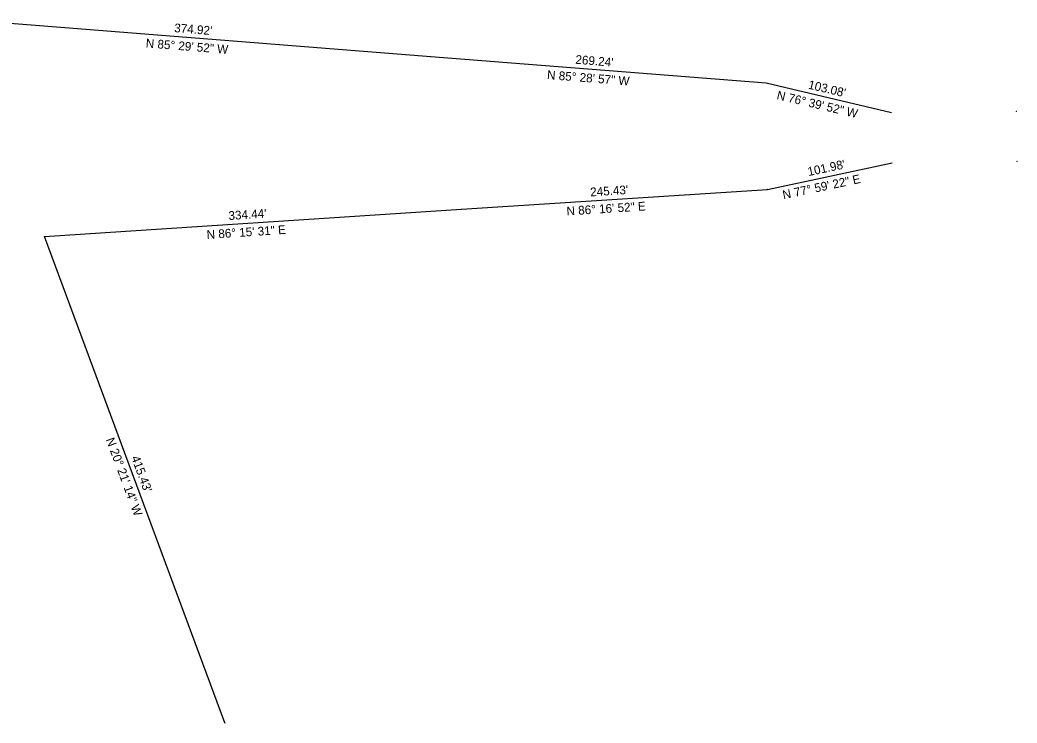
# Model space of a CAD drawing. Extents: x 179269 to 181170, y 300070 to 301262.
# Drawn here: x 180372 to 181170, y 300137 to 300700 of the extents above; entities that cross this region are included whole.
import ezdxf

# ---------------------------------------------------------------- set-up
doc = ezdxf.new("R2010")
doc.units = 0
for name, color, linetype in [('GK_Visualization', 7, 'Continuous'), ('RW_X_Fee_WL', 7, 'Continuous'), ('RW_X_Text', 7, 'Continuous')]:
    doc.layers.add(name, color=color, linetype=linetype)

msp = doc.modelspace()

# ---------------------------------------------------------------- linework, layer by layer
at = {"layer": 'GK_Visualization'}
for p, q in [((180700.4, 300670.33), (180326.63, 300699.76)), ((180700.4, 300670.33), (180326.63, 300699.76)), ((180700.33, 300670.27), (180700.46, 300670.4)), ((180700.33, 300670.4), (180700.46, 300670.27)), ((180968.79, 300649.13), (180700.4, 300670.33)), ((180968.79, 300649.13), (180700.4, 300670.33)), ((180968.73, 300649.06), (180968.86, 300649.19)), ((180968.73, 300649.19), (180968.86, 300649.06)), ((181069.09, 300625.35), (180968.79, 300649.13)), ((181069.09, 300625.35), (180968.79, 300649.13)), ((181169.02, 300626.51), (181169.15, 300626.64)), ((181169.02, 300626.64), (181169.15, 300626.51)), ((181069.03, 300625.28), (181069.16, 300625.42)), ((181069.03, 300625.42), (181069.16, 300625.28)), ((181169.51, 300586.51), (181169.64, 300586.64)), ((181169.51, 300586.64), (181169.64, 300586.51)), ((180969.83, 300564.13), (181069.58, 300585.35)), ((180969.83, 300564.13), (181069.58, 300585.35)), ((181069.52, 300585.29), (181069.65, 300585.42)), ((181069.52, 300585.42), (181069.65, 300585.29)), ((180724.92, 300548.21), (180969.83, 300564.13)), ((180724.92, 300548.21), (180969.83, 300564.13)), ((180969.77, 300564.07), (180969.9, 300564.2)), ((180969.77, 300564.2), (180969.9, 300564.07)), ((180391.19, 300526.39), (180724.92, 300548.21)), ((180391.19, 300526.39), (180724.92, 300548.21)), ((180724.85, 300548.15), (180724.99, 300548.28)), ((180724.85, 300548.28), (180724.99, 300548.15)), ((180391.12, 300526.32), (180391.25, 300526.46)), ((180391.12, 300526.46), (180391.25, 300526.32)), ((180535.68, 300136.9), (180391.19, 300526.39)), ((180535.68, 300136.9), (180391.19, 300526.39)), ((180535.62, 300136.83), (180535.75, 300136.96)), ((180535.62, 300136.96), (180535.75, 300136.83))]:
    msp.add_line(p, q, dxfattribs=at)
at = {"layer": 'RW_X_Fee_WL'}
for p, q in [((180700.4, 300670.33), (180326.63, 300699.76)), ((180968.79, 300649.13), (180700.4, 300670.33)), ((181069.09, 300625.35), (180968.79, 300649.13)), ((180969.83, 300564.13), (181069.58, 300585.35)), ((180724.92, 300548.21), (180969.83, 300564.13)), ((180391.19, 300526.39), (180724.92, 300548.21)), ((180535.68, 300136.9), (180391.19, 300526.39))]:
    msp.add_line(p, q, dxfattribs=at)

# ---------------------------------------------------------------- texts
at = {"layer": 'GK_Visualization'}
for s, p in [('EA708', (180699.81, 300670.33)), ('EA718', (180968.28, 300649.13)), ('EA714', (181168.57, 300626.57)), ('EA720', (181068.52, 300625.35)), ('EA713', (181169.06, 300586.58)), ('EA715', (181069.07, 300585.35)), ('EA717', (180969.32, 300564.13)), ('EA707', (180724.34, 300548.21)), ('EA704', (180390.61, 300526.39)), ('EA703', (180535.1, 300136.9))]:
    msp.add_text(s, height=0.14, dxfattribs=at).set_placement(p)
at = {"layer": 'RW_X_Text'}
for s, rotation, p in [("374.92'", 355.49789, (180494.92, 300690.02)), ('N 85%%d 29\' 52" W', 355.49789, (180472.14, 300677.77)), ("269.24'", 355.48257, (180816, 300664.71)), ('N 85%%d 28\' 57" W', 355.48257, (180793.28, 300652.46)), ("103.08'", 346.66443, (181002, 300644.85)), ('N 76%%d 39\' 52" W', 346.66443, (180976.84, 300636.43)), ("101.98'", 12.01061, (181002.81, 300574.73)), ('N 77%%d 59\' 22" E', 12.01061, (180982.76, 300556.15)), ("245.43'", 3.71896, (180828.23, 300558.44)), ("334.44'", 3.74143, (180538.77, 300539.55)), ('N 86%%d 16\' 52" E', 3.71896, (180809.29, 300543.18)), ('N 86%%d 15\' 31" E', 3.74143, (180521.29, 300524.37)), ('N 20%%d 21\' 14" W', 290.35387, (180440.3, 300363.82)), ("415.43'", 290.35387, (180460.58, 300349.39))]:
    msp.add_text(s, height=7, rotation=rotation, dxfattribs=at).set_placement(p)

doc.saveas('drawing.dxf')
